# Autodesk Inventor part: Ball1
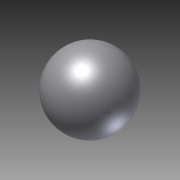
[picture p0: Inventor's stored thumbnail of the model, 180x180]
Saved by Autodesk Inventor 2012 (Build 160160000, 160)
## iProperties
Created: 2012-04
Part Number: Ball1
Material: Default
Document SubType Name: Modeling
Designer: Jonathan
Density: 1 g/cm^3
Mass: 1.07253 g
Surface Area: 5.06707 cm^2
Volume: 1.07253 cm^3
Author: Jonathan
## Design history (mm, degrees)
sketch "Sketch1"
  geometry: L1 (-6.35, 0)-(6.35, 0); A1 r 6.35 centre (0, 0) between (6.35, 0) and (-6.35, 0); 1 further point
  constraints: 2 end point, 2 point on circle, 1 centre point, 1 coincident, 1 horizontal
  dimensions: "d0" = 90 deg dimension on point (0, 0) A1.centre L1.end L1.start A1 L1; "d2" = 6.35 radius of A1
revolve "Revolution1" sketch "Sketch1" stored, may be unused: angle "d0" = 90 deg
body "Solid1"
